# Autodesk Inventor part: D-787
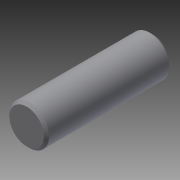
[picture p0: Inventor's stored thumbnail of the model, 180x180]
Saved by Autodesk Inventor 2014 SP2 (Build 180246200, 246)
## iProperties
Created: 2020-01
Part Number: D-787
Material: Generic
Catalog Web Link: www.cadenas.de
Description: Pin-Original Line - Standard Air Cylinders
Vendor: BIMBA
Document SubType Name: Modeling
Designer: psadmin
Manufacturer: BIMBA
Mass: 0.15599 g
Surface Area: 1.78407 cm^2
Volume: 0.15599 cm^3
Density: 1 g/cm^3
Appearance: PSOLRGB-192-192-192
Category: PARTsolutions
Company: BIMBA
Title: D-787
Author: Cadenas PARTsolutions
Comments: Original Line - Standard Air Cylinders
PSOL_IDENT_0: {$CADENAS_DATA\23d-libs\bimba\bimba_brand\bimba_imperial\bimba_full_line\original_line_cylinders\sta
PSOL_IDENT_1: ndard_air_cylinders\pin.prj},147 {VTYP=3D},{NB=D-787},{LINA=D-787},{NN=Pin},{DATE=23.12.2019 10:36:4
PSOL_IDENT_2: 7},{GEOMDATE=15.02.2011 00:00:00},{VERSION=},{LINEID=20},{WBVAR=},{WBNUMERIC=}  {NB=D-787},{LINA=D-7
PSOL_IDENT_3: 87},{KT=DUMMY},{PN=D-787},{DIA=0.15625},{L=0.5000}
NN: Pin
NT: Original Line - Standard Air Cylinders
NB: D-787
NBSYN: $PN.
LINA: D-787
PN: D-787
DIA: 0.15625
L: 0.5
SUPPLIER: BIMBA
ARTICLENO: D-787
BOMINFO: D-787
CREATOR: CADENAS GmbH
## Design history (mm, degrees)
sketch "Sketch_1"
  geometry: L1 (0, -6.35)-(0, 6.35); L2 (0, 6.35)-(1.733, 6.35); L3 (1.733, 6.35)-(1.984, 6.099); L4 (1.984, 6.099)-(1.984, -5.994); L5 (1.984, -5.994)-(1.629, -6.35); L6 (1.629, -6.35)-(0, -6.35); L7 (0, -6.35)-(0, 6.35)
  constraints: 14 end point
revolve "Revolution1" sketch "Sketch_1" stored, may be unused: angle "d0" = 360 deg
node "dia1_XY"
node "dia1_YZ"
node "dia1_ZX"
node "dia1_X"
node "dia1_Y"
node "dia1_Z"
node "dia1_Center"
node "dia2_XY"
node "dia2_YZ"
node "dia2_ZX"
node "dia2_X"
node "dia2_Y"
node "dia2_Z"
node "dia2_Center"
node "pin_XY"
node "pin_YZ"
node "pin_ZX"
node "pin_X"
node "pin_Y"
node "pin_Z"
node "pin_Center"
node "pin1_XY"
node "pin1_YZ"
node "pin1_ZX"
node "pin1_X"
node "pin1_Y"
node "pin1_Z"
node "pin1_Center"
node "pin2_XY"
node "pin2_YZ"
node "pin2_ZX"
node "pin2_X"
node "pin2_Y"
node "pin2_Z"
node "pin2_Center"
body "Solid1"
